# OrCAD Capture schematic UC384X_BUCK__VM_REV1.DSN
size A3; title: UC384x_BUCK_Voltage Mode; rev: 2.0
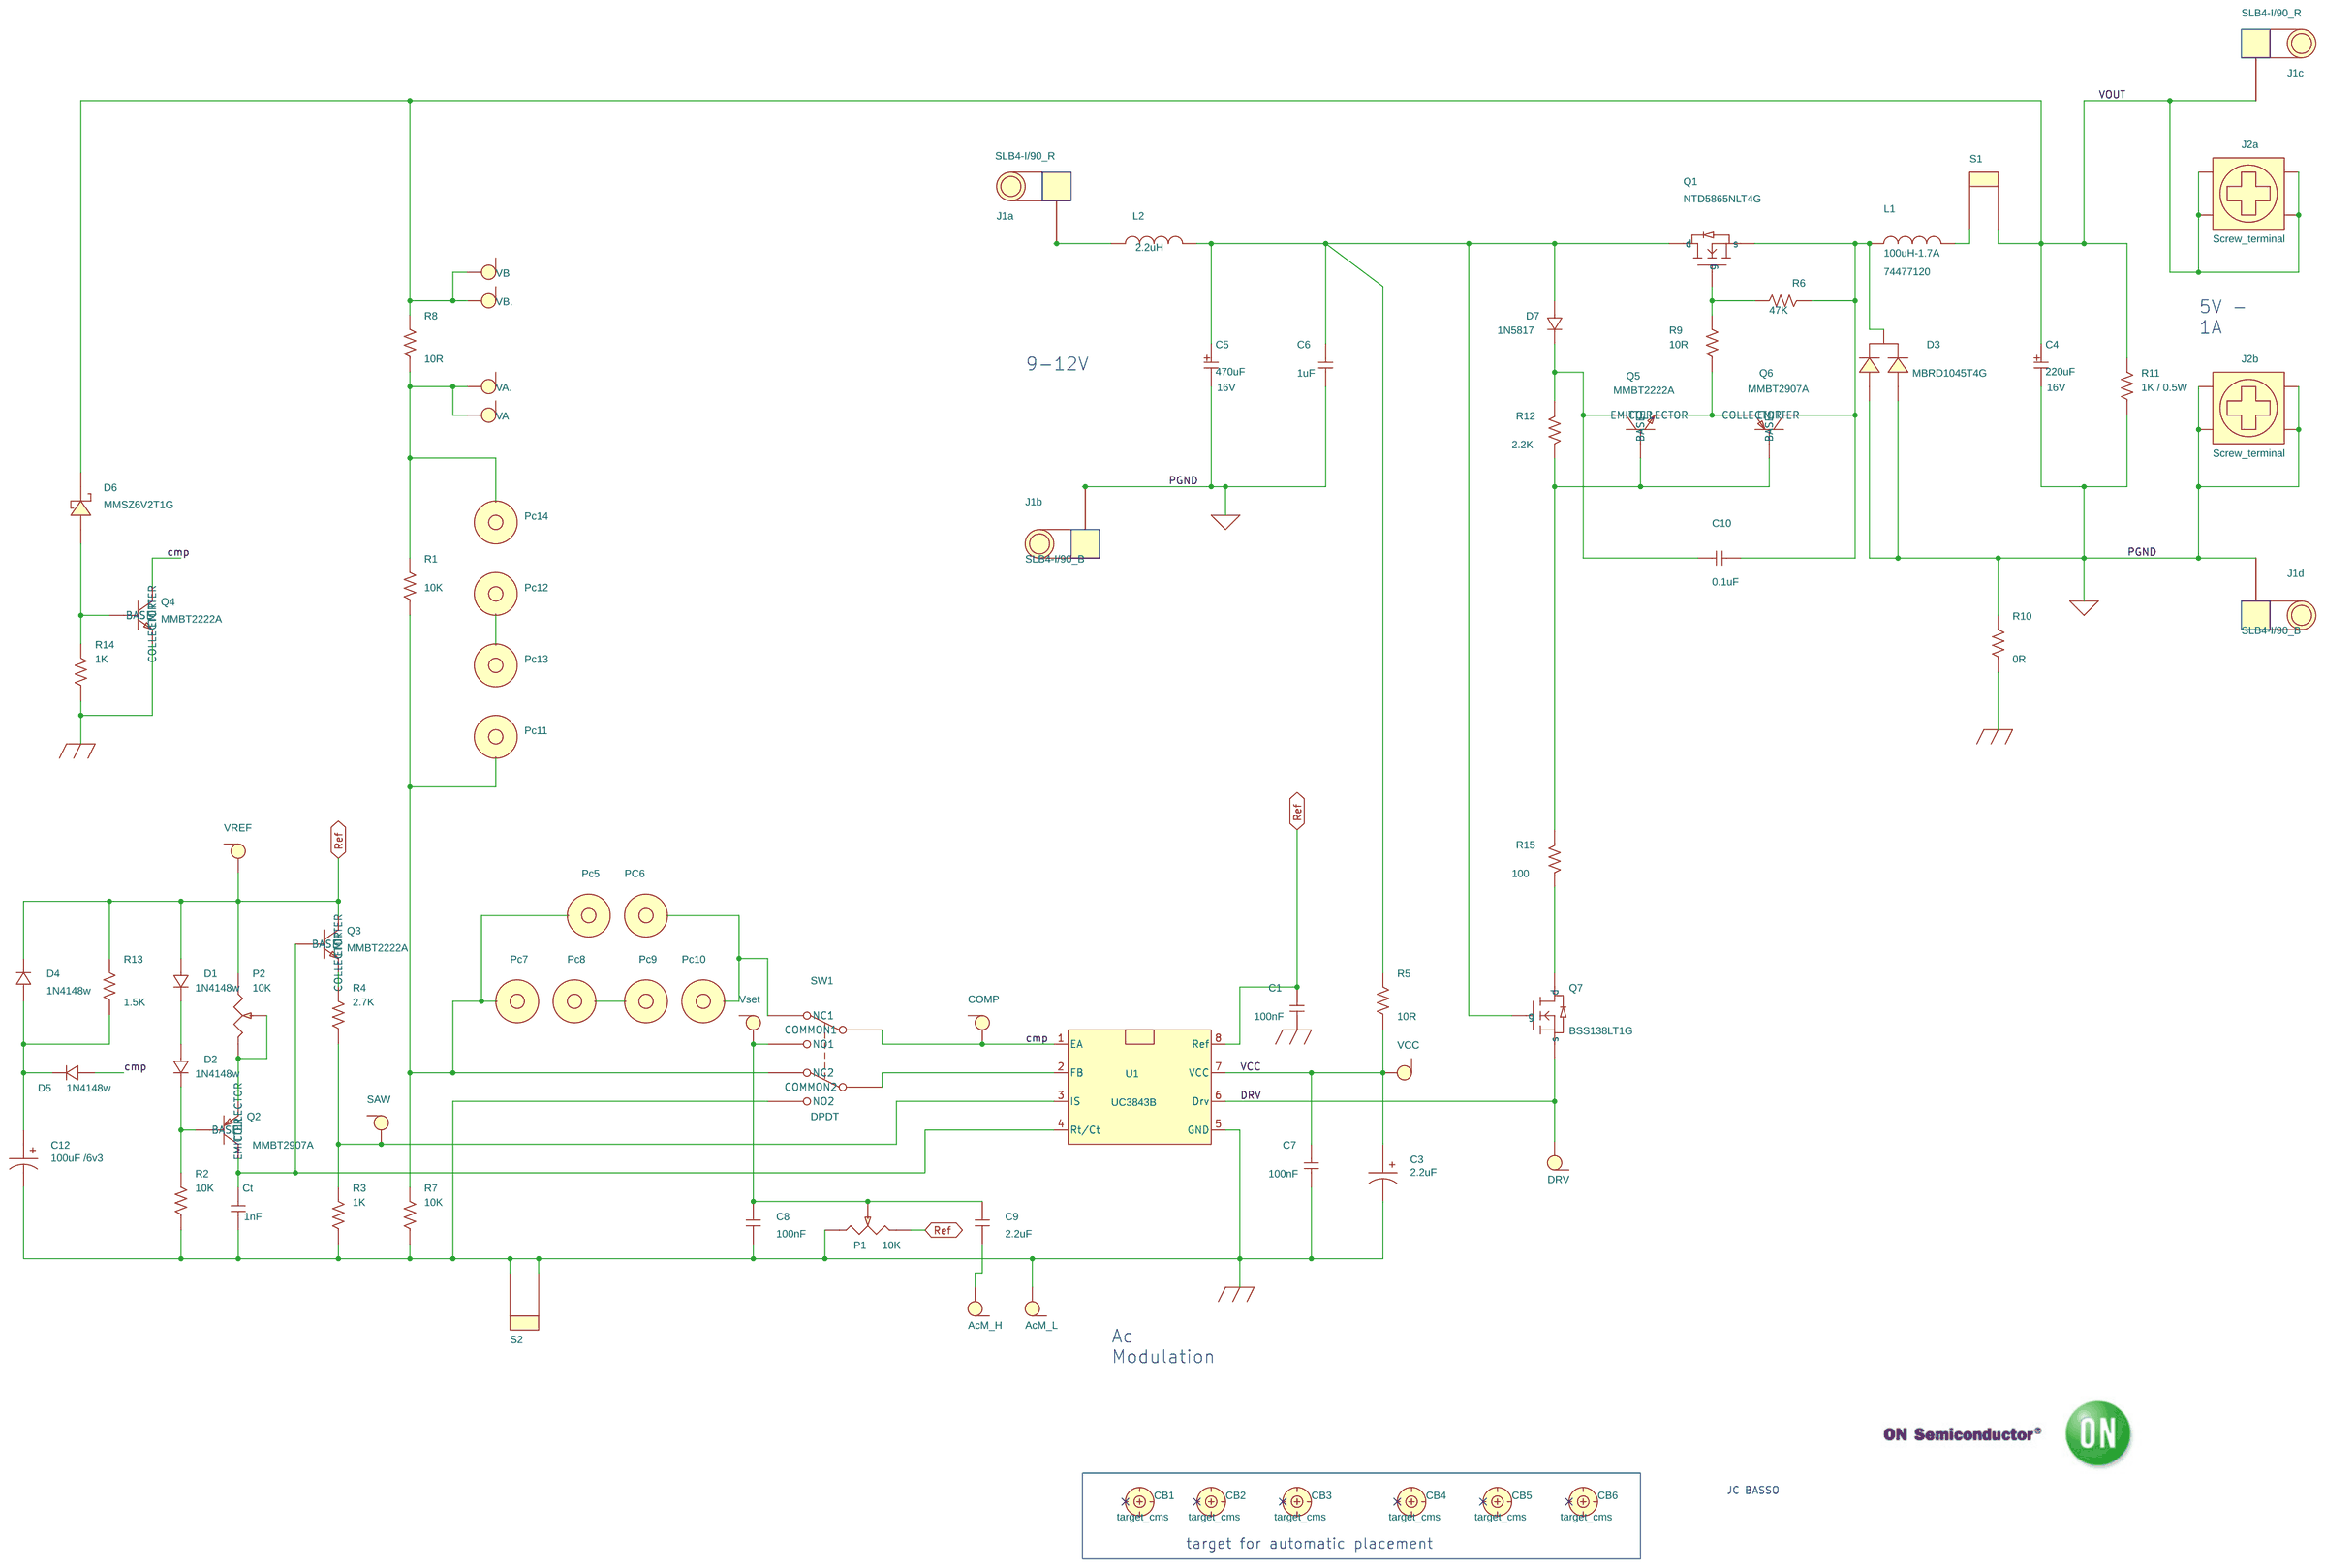
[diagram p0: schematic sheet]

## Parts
AcM_H  TEST POINT  [TP]
AcM_L  TEST POINT  [TP]
C1  100nF  [0805]
C3  2.2uF  [capa_ch_d5_h11_p2]
C4  220uF  [CAPA_ch_D8_H12_P3v5]
C5  470uF  [capa_ch_d10_h13_p5]
C6  1uF  [0805]
C7  100nF  [0805]
C8  100nF  [0805]
C9  2.2uF  [0805]
C10  0.1uF  [0805]
C12  100uF /6v3  [capa_ch_d5_h11_p2]
CB1  target_cms  [mire_low]
CB2  target_cms  [mire_low]
CB3  target_cms  [mire_low]
CB4  target_cms  [mire_low]
CB5  target_cms  [mire_low]
CB6  target_cms  [mire_low]
COMP  TEST POINT  [TP]
Ct  1nF  [0805]
D1  1N4148w  [SOD123]
D2  1N4148w  [SOD123]
D3  MBRD1045T4G  [DPAK_TO252]
D4  1N4148w  [SOD123]
D5  1N4148w  [SOD123]
D6  MMSZ6V2T1G  [SOD123]
D7  1N5817  [DO41]
DRV  TEST POINT  [TP]
J1a  SLB4-I/90_R  [BANANE_4MM_SLB4]
J1b  SLB4-I/90_B  [BANANE_4MM_SLB4]
J1c  SLB4-I/90_R  [BANANE_4MM_SLB4]
J1d  SLB4-I/90_B  [BANANE_4MM_SLB4]
J2a  Screw_terminal  [pc_7701]
J2b  Screw_terminal  [pc_7701]
L1  100uH-1.7A  [self_WE-PD-1260]
L2  2.2uH  [self_SRN2009]
P1  10K  [potar_12t_3266W]
P2  10K  [potar_12t_3266W]
Pc5  D  [PLOT_5380598-2]
PC6  D  [PLOT_5380598-2]
Pc7  D  [PLOT_5380598-2]
Pc8  D  [PLOT_5380598-2]
Pc9  D  [PLOT_5380598-2]
Pc10  D  [PLOT_5380598-2]
Pc11  D  [PLOT_5380598-2]
Pc12  D  [PLOT_5380598-2]
Pc13  D  [PLOT_5380598-2]
Pc14  D  [PLOT_5380598-2]
Q1  NTD5865NLT4G  [DPAK_TO252]
Q2  MMBT2907A  [SOT23]
Q3  MMBT2222A  [SOT23]
Q4  MMBT2222A  [SOT23]
Q5  MMBT2222A  [SOT23]
Q6  MMBT2907A  [SOT23]
Q7  BSS138LT1G  [SOT23]
R1  10K  [0805]
R2  10K  [0805]
R3  1K  [0805]
R4  2.7K  [0805]
R5  10R  [0805]
R6  47K  [0805]
R7  10K  [0805]
R8  10R  [0805]
R9  10R  [0805]
R10  0R  [0805]
R11  1K / 0.5W  [RC21U]
R12  2.2K  [0805]
R13  1.5K  [0805]
R14  1K  [0805]
R15  100  [0805]
S1  Strap  [jumper400h]
S2  Strap  [jumper400h]
SAW  TEST POINT  [TP]
SW1  DPDT  [sw_76SD01ST]
U1  UC3843B  [DIP8_sup]
VA  TEST POINT  [TP]
VA.  TEST POINT  [TP]
VB  TEST POINT  [TP]
VB.  TEST POINT  [TP]
VCC  TEST POINT  [TP]
VREF  TEST POINT  [TP]
Vset  TEST POINT  [TP]

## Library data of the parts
AcM_H AcM_L COMP DRV SAW VA VA. VB VB. VCC VREF Vset = TEST_POINT_0_v2
C1 C6-C10 Ct = C: COMPFIXED: NO; COMPGROUP: 0; COMPHEIGHT: 0.000; COMPKEY: NO; COMPLOC: [5662.500,337.500]; COMPLOCKED: NO; COMPROT: 270; COMPSIDE: BOT; DECOUPLER: NO; MEMORY: NO; VOLTAGE: 25V
C3 C12 = CAP_POL
C4 = C_elect_0: PART_NUMBER: UPW1E221MPD1TD; Voltage: 16V
C5 = C_elect_0: PART_NUMBER: 860080375014; Voltage: 16V
CB1-CB6 = target_cms
D1 D2 D4 D5 = D1N4148_2
D3 = dual_diodeAAK
D6 = DIODE_SCHOTTKY_0
D7 = 1N5817_0
J1a J1b J1c J1d = HEADER_1_0
J2a J2b = 4_HEADER_0
L1 = CHOKE: PN: 74477120
L2 = L: COMPFIXED: NO; COMPGROUP: 0; COMPHEIGHT: 0.000; COMPKEY: NO; COMPLOC: [6725.000,1075.000]; COMPLOCKED: NO; COMPROT: 270; COMPSIDE: TOP; DECOUPLER: NO; MEMORY: NO; PART_NUMBER: SRN2009T-2R2M
P1 P2 = RESISTOR_VAR
Pc5 PC6 Pc7-Pc14 = T_POINT_R_0
Q1 = NMOS_2: PART_NUMBER: IPA50R250CP
Q2 Q6 = 2N2907A_0
Q3-Q5 = 2N2222A_0
Q7 = NMOS_1
R1-R9 R13 R14 = R: COMPFIXED: NO; COMPGROUP: 0; COMPHEIGHT: 0.000; COMPKEY: NO; COMPLOC: [1787.500,750.000]; COMPLOCKED: NO; COMPROT: 90; COMPSIDE: TOP; DECOUPLER: NO; FPLIST: AX/RC05,SM/C_1206H,AX/RC07,AX/RC07_D; MEMORY: NO; VOLTAGE: 200v
R10 = R: COMPFIXED: NO; COMPGROUP: 0; COMPHEIGHT: 0.000; COMPKEY: NO; COMPLOC: [1787.500,750.000]; COMPLOCKED: NO; COMPROT: 90; COMPSIDE: TOP; DECOUPLER: NO; FPLIST: AX/RC05,SM/C_1206H,AX/RC07,AX/RC07_D; MEMORY: NO; VOLTAGE: ?v
R11 = R: COMPFIXED: NO; COMPGROUP: 0; COMPHEIGHT: 0.000; COMPKEY: NO; COMPLOC: [1787.500,750.000]; COMPLOCKED: NO; COMPROT: 90; COMPSIDE: TOP; DECOUPLER: NO; FPLIST: AX/RC05,SM/C_1206H,AX/RC07,AX/RC07_D; MEMORY: NO; PART_NUMBER: NC; VOLTAGE: 200v
R12 R15 = R: COMPFIXED: NO; COMPGROUP: 0; COMPHEIGHT: 0.000; COMPKEY: NO; COMPLOC: [4650.000,400.000]; COMPLOCKED: NO; COMPROT: 180; COMPSIDE: TOP; DECOUPLER: NO; FPLIST: AX/RC07_D,AX/RC07,SM/C_1206H,AX/RC05; MEMORY: NO; PART_NUMBER: LVR03R0800FE12
S1 S2 = TEST_POINT_0
SW1 = SW_DPDT_SM_0
U1 = UC3845B

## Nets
GND_EARTH: AcM_L.1 C1.2 C3.2 C7.2 C8.1 C12.2 Ct.2 P1.1(A) Q4.2(EMITTER) R2.1 R3.1 R7.1 R10.1 R14.1 S2.1 S2.2 SW1.2(NO2) U1.5(GND)
GND_SIGNAL: C4.2(-) C5.2(-) C6.2 D3.1(A1) D3.3(A2) J1b.1 J1b.2 J1b.3 J1b.4 J1b.5 J1d.1 J1d.2 J1d.3 J1d.4 J1d.5 J2b.1 J2b.2 J2b.3 J2b.4 R10.2 R11.1
VCC: C3.1 C7.1 R5.1 U1.7(VCC) VCC.1
cmp: COMP.1 D5.2 Q4.3(COLLECTOR) SW1.C1(COMMON1) U1.1(EA)
DRV: DRV.1 Q7.2(s) U1.6(Drv)
Ref: C1.1 D1.2 D4.1 P1.3(B) P2.1(A) Q3.3(COLLECTOR) R13.2 U1.8(Ref) VREF.1
VOUT: C4.1(+) D6.1(CATHODE) J1c.1 J1c.2 J1c.3 J1c.4 J1c.5 J2a.1 J2a.2 J2a.3 J2a.4 R8.2 R11.2 S1.1 VB.1 VB..1
N12289703: C5.1(+) C6.1 D7.2 L2.2 Q1.2(d) Q7.1(g) R5.2
N12295469: Ct.1 Q2.3(COLLECTOR) Q3.1(BASE) U1.4(Rt/Ct)
N12295845: R3.2 R4.1 SAW.1 U1.3(IS)
N12298127: Pc5.1(TP) Pc7.1(TP) Pc11.1(TP) R1.1 R7.2 SW1.22(NC2)
N12299817: Pc8.1(TP) Pc9.1(TP)
N12299821: PC6.1(TP) Pc10.1(TP) SW1.11(NC1)
N12517793: J1a.1 J1a.2 J1a.3 J1a.4 J1a.5 L2.1
N12518780: Q7.3(d) R15.2
N12519598: Q5.1(BASE) Q6.1(BASE) R12.2 R15.1
N12520738: C10.1 D7.1 Q5.3(COLLECTOR) R12.1
N12521657: Q5.2(EMITTER) Q6.2(EMITTER) R9.1
N12521671: Q1.1(g) R6.2 R9.2
N12521759: C10.2 D3.2(C) L1.1 Q1.3(s) Q6.3(COLLECTOR) R6.1
N12522225: L1.2 S1.2
N12524308: C12.1 D4.2 D5.1 R13.1
N12524599: D6.2(ANODE) Q4.1(BASE) R14.2
N12543157: Pc12.1(TP) Pc13.1(TP)
N12543161: Pc14.1(TP) R1.2 R8.1 VA.1 VA..1
N12544501: AcM_H.1 C9.1
N12544892: C8.2 C9.2 P1.2(WIPER) SW1.1(NO1) Vset.1
N12545642: SW1.C2(COMMON2) U1.2(FB)
N12547004: Q3.2(EMITTER) R4.2
N12548180: P2.2(WIPER) P2.3(B) Q2.2(EMITTER)
N12548483: D2.1 Q2.1(BASE) R2.2
N12548948: D1.1 D2.2

Not connected (* = marked no-connect by the designer): CB1 1*; CB2 1*; CB3 1*; CB4 1*; CB5 1*; CB6 1*

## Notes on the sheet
- 5V -
  1A
- 9-12V
- Ac
  Modulation
- JC BASSO
- target for automatic placement
